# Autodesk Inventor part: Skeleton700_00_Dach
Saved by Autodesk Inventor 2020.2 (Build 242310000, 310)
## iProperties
_SkeletonDoc: Frame Skeleton File
_Version: 15.0.0
Manager: www.cadconsulting.pl
Company: Fabian Stasiak CAD Consulting
Created: 2017-03
Part Number: Skeleton700_00_Dach
Material: Ogólne
Document SubType Name: Modeling
Designer: F.Stasiak
Density: 1 g/cm^3
Appearance: Domyślne
Catalog Web Link: www.expertbooks.pl
Author: F.Stasiak
Subject: Zbiór ćwiczeń. Autodesk Inventor 2020. Kurs Professional
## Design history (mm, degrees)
sketch "Szkielet odniesienia"
